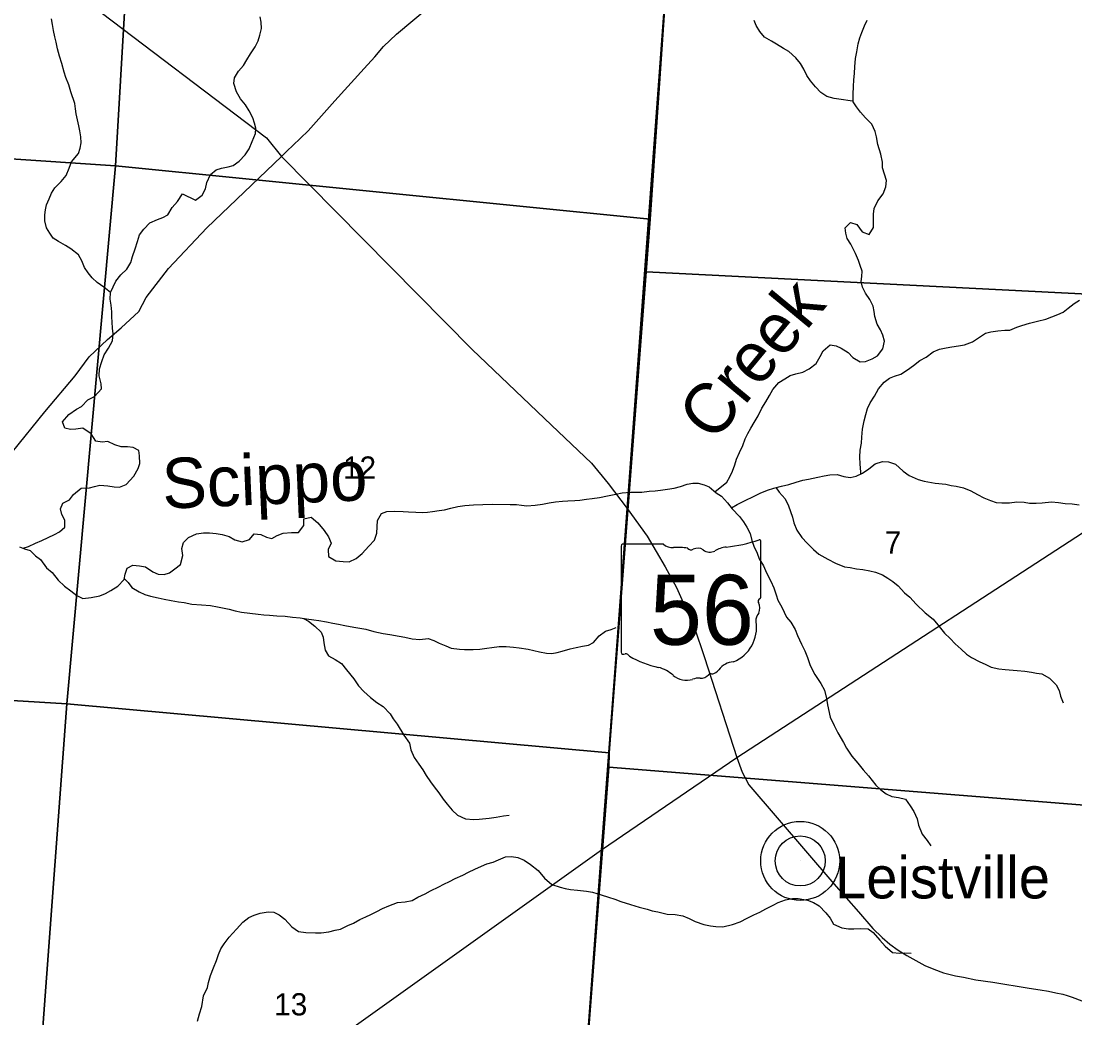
# Model space of a CAD drawing. Extents: x 1643459 to 2064572, y 425441 to 780708.
# Drawn here: x 1865157 to 1875648, y 555768 to 565687 of the extents above; entities that cross this region are included whole.
import ezdxf

# ---------------------------------------------------------------- set-up
doc = ezdxf.new("R2010")
doc.units = 0
for name, color, linetype in [('GE_P_Alignment_100_Curve_Data', 7, 'Continuous'), ('GM_X_Adjacent_County', 7, 'Continuous'), ('GM_X_City_Street', 7, 'Continuous'), ('GM_X_Interchange_Ramps', 7, 'Continuous'), ('GM_X_Major_River_Text', 7, 'Continuous'), ('GM_X_Rail_Line', 7, 'Continuous'), ('GM_X_State_Route', 7, 'Continuous'), ('GM_X_Township_ROW', 7, 'Continuous'), ('GM_X_US_Route', 7, 'Continuous'), ('PM_P_Cells', 7, 'Continuous'), ('RD_X_Text', 7, 'Continuous'), ('ST_Details', 7, 'Continuous')]:
    doc.layers.add(name, color=color, linetype=linetype)

msp = doc.modelspace()

# ---------------------------------------------------------------- linework, layer by layer
at = {"layer": 'GE_P_Alignment_100_Curve_Data'}
for radius in [393, 249]:
    msp.add_circle((1872913, 557330), radius, dxfattribs=at)
at = {"layer": 'GM_X_City_Street'}
for points in [[(1843248, 570866), (1845450, 570731), (1847249, 570616), (1849898, 570458), (1849968, 570443), (1850122, 570435), (1851230, 570338), (1851365, 570353), (1852697, 570271), (1853339, 570225), (1855635, 570110), (1855712, 570098), (1858092, 569921), (1858213, 569927), (1860143, 569780), (1863642, 569513), (1864565, 569438), (1866325, 569307), (1871699, 568906), (1871789, 568904), (1871189, 560836), (1870936, 557440), (1870510, 551709)], [(1891038, 535264), (1876915, 536283), (1869365, 536798), (1869625, 540128), (1869975, 544893), (1870294, 549051), (1870510, 551709), (1870936, 557440), (1871189, 560836), (1871789, 568904), (1872185, 568870), (1872796, 568823), (1874538, 568690), (1875303, 568632), (1876334, 568559), (1877076, 568501), (1882154, 568081), (1884543, 567856)]]:
    msp.add_lwpolyline(points, dxfattribs=at)
at = {"layer": 'GM_X_Major_River_Text'}
for points in [[(1867863, 564450), (1868014, 564595), (1868279, 564895), (1868572, 565216), (1868677, 565332), (1868764, 565434), (1868893, 565558), (1869238, 565847), (1869691, 566239), (1870084, 566568), (1870264, 566733), (1870344, 566797), (1870453, 566895), (1870614, 567065), (1871125, 567416)], [(1867749, 564341), (1867806, 564396), (1867863, 564450)], [(1864004, 560421), (1864119, 560508), (1864470, 560783), (1864563, 560848), (1864658, 560940), (1864778, 561043), (1865072, 561400), (1865395, 561800), (1865696, 562158), (1865834, 562345), (1866017, 562519), (1866154, 562636), (1866330, 562797), (1866402, 562938), (1866626, 563225), (1867005, 563630), (1867749, 564341)], [(1870510, 551709), (1870936, 557440)]]:
    msp.add_lwpolyline(points, dxfattribs=at)
at = {"layer": 'GM_X_Rail_Line'}
msp.add_line((1872913, 557330), (1872913, 557330), dxfattribs=at)
at = {"layer": 'GM_X_State_Route'}
for points in [[(1860886, 569691), (1860960, 569686), (1866313, 569289), (1866393, 569280), (1866098, 564247), (1860536, 564618)], [(1871776, 568888), (1871419, 563717), (1866098, 564247), (1866393, 569280)], [(1876329, 568549), (1877071, 568491), (1876694, 562925), (1871379, 563191), (1871419, 563717), (1871776, 568888)], [(1866098, 564247), (1865614, 558892), (1860164, 559226), (1860536, 564618)], [(1871419, 563717), (1871379, 563191), (1871012, 558406), (1865614, 558892), (1866098, 564247)], [(1876694, 562925), (1876279, 557842), (1871008, 558262), (1871012, 558406), (1871379, 563191)], [(1860164, 559226), (1865614, 558892), (1865211, 553484), (1859790, 553839)], [(1865614, 558892), (1871012, 558406), (1871008, 558262), (1870602, 552995), (1865211, 553484)], [(1871008, 558262), (1876279, 557842), (1875834, 552347), (1870578, 552653), (1870602, 552995)]]:
    msp.add_lwpolyline(points, close=True, dxfattribs=at)
at = {"layer": 'GM_X_US_Route'}
for points in [[(1866048, 562988), (1865982, 563040), (1865916, 563085), (1865865, 563133), (1865825, 563183), (1865787, 563236), (1865761, 563300), (1865727, 563361), (1865652, 563421), (1865598, 563454), (1865529, 563493), (1865477, 563527), (1865444, 563577), (1865410, 563630), (1865394, 563698), (1865394, 563758), (1865400, 563808), (1865411, 563858), (1865437, 563920), (1865459, 563974), (1865494, 564028), (1865557, 564090), (1865607, 564150), (1865636, 564224), (1865658, 564286), (1865727, 564368), (1865745, 564422), (1865755, 564476), (1865753, 564536), (1865743, 564594), (1865731, 564644), (1865717, 564703), (1865705, 564763), (1865699, 564813), (1865691, 564867), (1865651, 564982), (1865631, 565052), (1865603, 565127), (1865587, 565179), (1865563, 565265), (1865539, 565338), (1865521, 565410), (1865505, 565478), (1865493, 565529), (1865481, 565593), (1865471, 565653), (1865459, 565708)], [(1866764, 563967), (1866893, 563906), (1866958, 563956), (1866994, 564017), (1867007, 564082), (1867041, 564159), (1867098, 564207), (1867152, 564223), (1867217, 564236), (1867268, 564250), (1867328, 564292), (1867387, 564356), (1867428, 564417), (1867456, 564489), (1867492, 564567), (1867493, 564622), (1867481, 564672), (1867465, 564726), (1867428, 564795), (1867392, 564853), (1867342, 564914), (1867301, 564984), (1867275, 565066), (1867282, 565121), (1867320, 565190), (1867371, 565246), (1867403, 565300), (1867442, 565360), (1867486, 565432), (1867517, 565492), (1867535, 565546), (1867549, 565614), (1867547, 565678), (1867537, 565729)], [(1872064, 561003), (1872183, 561099), (1872213, 561151), (1872240, 561209), (1872262, 561271), (1872278, 561327), (1872309, 561393), (1872341, 561465), (1872366, 561529), (1872392, 561583), (1872420, 561635), (1872455, 561693), (1872493, 561759), (1872532, 561835), (1872572, 561899), (1872607, 561961), (1872639, 562021), (1872700, 562090), (1872759, 562126), (1872813, 562162), (1872870, 562178), (1872939, 562195), (1873001, 562227), (1873072, 562280), (1873111, 562348), (1873141, 562406), (1873212, 562466), (1873270, 562457), (1873321, 562433), (1873389, 562390), (1873436, 562338), (1873510, 562295), (1873563, 562299), (1873630, 562326), (1873684, 562356), (1873735, 562426), (1873751, 562502), (1873737, 562562), (1873711, 562615), (1873679, 562671), (1873655, 562746), (1873649, 562798), (1873639, 562852), (1873605, 562918), (1873564, 562979), (1873534, 563039), (1873520, 563095), (1873526, 563146), (1873529, 563198), (1873511, 563254), (1873492, 563306), (1873462, 563373), (1873416, 563467), (1873382, 563524), (1873368, 563576), (1873362, 563630), (1873412, 563684), (1873477, 563663), (1873529, 563591), (1873600, 563564), (1873641, 563634), (1873641, 563765), (1873649, 563823), (1873686, 563899), (1873738, 563968), (1873765, 564038), (1873771, 564101), (1873753, 564163), (1873733, 564227), (1873731, 564283), (1873715, 564362), (1873687, 564458), (1873671, 564535), (1873659, 564589), (1873625, 564663), (1873562, 564726), (1873514, 564782), (1873474, 564833), (1873441, 564885), (1873441, 564958), (1873444, 565038), (1873446, 565098), (1873452, 565168), (1873456, 565232), (1873464, 565316), (1873475, 565381), (1873491, 565461), (1873507, 565519), (1873528, 565573), (1873552, 565641), (1873580, 565697)], [(1873441, 564889), (1873411, 564892), (1873322, 564906), (1873250, 564917), (1873177, 564937), (1873118, 564976), (1873066, 565034), (1873014, 565091), (1872979, 565145), (1872949, 565210), (1872915, 565266), (1872871, 565323), (1872800, 565383), (1872748, 565416), (1872677, 565459), (1872627, 565487), (1872558, 565528), (1872512, 565584), (1872475, 565643), (1872455, 565693)], [(1865179, 560441), (1865230, 560458), (1865300, 560491), (1865365, 560517), (1865426, 560547), (1865488, 560578), (1865539, 560606), (1865591, 560650), (1865592, 560720), (1865561, 560778), (1865551, 560835), (1865574, 560891), (1865639, 560924), (1865679, 560976), (1865756, 561038), (1865837, 561043), (1865889, 561055), (1865940, 561070), (1866019, 561064), (1866085, 561051), (1866138, 561049), (1866204, 561077), (1866279, 561160), (1866322, 561234), (1866340, 561284), (1866336, 561362), (1866328, 561413), (1866274, 561443), (1866215, 561450), (1866153, 561452), (1866090, 561471), (1866020, 561503), (1865965, 561498), (1865900, 561508), (1865856, 561579), (1865771, 561635), (1865703, 561626), (1865650, 561624), (1865592, 561637), (1865568, 561701), (1865632, 561773), (1865707, 561824), (1865758, 561852), (1865822, 561920), (1865887, 561951), (1865958, 562027), (1865954, 562077), (1865934, 562156), (1865936, 562226), (1865961, 562300), (1865985, 562366), (1866026, 562434), (1866066, 562504), (1866074, 562574), (1866068, 562632), (1866064, 562690), (1866059, 562744), (1866059, 562795), (1866053, 562859), (1866043, 562921), (1866047, 562985), (1866100, 563099), (1866150, 563161), (1866209, 563217), (1866248, 563285), (1866266, 563345), (1866294, 563421), (1866315, 563495), (1866335, 563561), (1866378, 563617), (1866440, 563678), (1866515, 563714), (1866568, 563734), (1866618, 563759), (1866661, 563833), (1866713, 563893), (1866764, 563967)], [(1873518, 561181), (1873516, 561198), (1873510, 561280), (1873506, 561348), (1873511, 561417), (1873523, 561487), (1873525, 561547), (1873533, 561625), (1873548, 561709), (1873566, 561773), (1873584, 561833), (1873609, 561889), (1873653, 561955), (1873694, 562029), (1873748, 562093), (1873801, 562133), (1873851, 562154), (1873914, 562174), (1873981, 562218), (1874040, 562261), (1874104, 562309), (1874167, 562343), (1874236, 562396), (1874298, 562424), (1874365, 562435), (1874424, 562445), (1874488, 562455), (1874549, 562466), (1874628, 562494), (1874699, 562543), (1874757, 562583), (1874810, 562595), (1874881, 562604), (1874949, 562610), (1875000, 562613), (1875068, 562641), (1875119, 562659), (1875194, 562682), (1875275, 562700), (1875359, 562721), (1875418, 562743), (1875479, 562766), (1875529, 562792), (1875580, 562830), (1875641, 562878), (1875693, 562909)], [(1872230, 560843), (1872287, 560878), (1872364, 560917), (1872449, 560957), (1872516, 560989), (1872589, 561018), (1872649, 561038), (1872726, 561059), (1872799, 561077), (1872872, 561098), (1872940, 561118), (1872995, 561130), (1873088, 561149), (1873153, 561162), (1873207, 561172), (1873282, 561176), (1873348, 561155), (1873411, 561145), (1873470, 561158), (1873532, 561188), (1873597, 561233), (1873658, 561281), (1873733, 561305), (1873793, 561300), (1873862, 561278), (1873938, 561207), (1873999, 561164), (1874086, 561124), (1874148, 561109), (1874255, 561090), (1874362, 561078), (1874415, 561065), (1874467, 561059), (1874538, 561042), (1874613, 561014), (1874677, 560977), (1874742, 560944), (1874808, 560916), (1874863, 560897), (1874919, 560893), (1874998, 560894), (1875069, 560904), (1875141, 560899), (1875196, 560891), (1875261, 560890), (1875321, 560894), (1875416, 560903), (1875485, 560897), (1875549, 560888), (1875620, 560882), (1875689, 560875)], [(1868245, 560492), (1868215, 560428), (1868217, 560360), (1868291, 560317), (1868362, 560309), (1868424, 560306), (1868493, 560340), (1868554, 560388), (1868619, 560461), (1868675, 560523), (1868700, 560593), (1868702, 560655), (1868706, 560719), (1868745, 560787), (1868797, 560807), (1868870, 560812), (1868961, 560808), (1869013, 560803), (1869086, 560801), (1869151, 560798), (1869203, 560802), (1869254, 560806), (1869318, 560817), (1869373, 560825), (1869435, 560842), (1869504, 560856), (1869575, 560866), (1869660, 560873), (1869753, 560876), (1869852, 560880), (1870025, 560878), (1870088, 560876), (1870138, 560871), (1870193, 560865), (1870276, 560870), (1870346, 560880), (1870415, 560894), (1870476, 560903), (1870546, 560911), (1870599, 560912), (1870668, 560916), (1870720, 560919), (1870785, 560929), (1870841, 560937), (1870914, 560948), (1870995, 560964), (1871078, 560979), (1871140, 560993), (1871223, 560998), (1871278, 560998), (1871336, 561001), (1871409, 561009), (1871468, 561014), (1871522, 561020), (1871591, 561029), (1871658, 561039), (1871722, 561057), (1871787, 561078), (1871844, 561088), (1871896, 561089), (1871957, 561071), (1872007, 561052), (1872078, 560992), (1872128, 560959), (1872189, 560893), (1872237, 560834), (1872309, 560759), (1872348, 560703), (1872380, 560651), (1872414, 560588), (1872430, 560520), (1872452, 560462), (1872486, 560391), (1872506, 560337), (1872547, 560268), (1872579, 560196), (1872619, 560113), (1872649, 560049), (1872675, 559978), (1872691, 559926), (1872730, 559854), (1872778, 559757), (1872818, 559705), (1872862, 559632), (1872887, 559572), (1872925, 559487), (1872959, 559421), (1872987, 559356), (1873009, 559286), (1873031, 559236), (1873059, 559185), (1873118, 559095), (1873156, 559030), (1873176, 558946), (1873184, 558882), (1873210, 558761), (1873250, 558679), (1873288, 558604), (1873345, 558509), (1873373, 558451), (1873427, 558374)], [(1872673, 561044), (1872702, 560999), (1872762, 560933), (1872796, 560864), (1872816, 560806), (1872835, 560750), (1872849, 560695), (1872881, 560623), (1872929, 560550), (1872981, 560492), (1873044, 560429), (1873098, 560383), (1873189, 560334), (1873264, 560293), (1873355, 560258), (1873409, 560250), (1873474, 560237), (1873536, 560231), (1873607, 560218), (1873663, 560202), (1873732, 560177), (1873785, 560145), (1873835, 560110), (1873887, 560068), (1873950, 559999), (1874004, 559955), (1874067, 559884), (1874157, 559799), (1874238, 559736), (1874284, 559678), (1874351, 559597), (1874405, 559543), (1874456, 559490), (1874514, 559438), (1874567, 559387), (1874619, 559355), (1874702, 559310), (1874754, 559287), (1874815, 559259), (1874889, 559240), (1874954, 559234), (1875073, 559225), (1875150, 559218), (1875215, 559208), (1875265, 559200), (1875317, 559191), (1875396, 559150), (1875461, 559084), (1875491, 559027), (1875505, 558969), (1875529, 558903)], [(1865141, 560456), (1865191, 560436), (1865248, 560418), (1865300, 560365), (1865350, 560329), (1865409, 560246), (1865467, 560201), (1865526, 560123), (1865590, 560064), (1865653, 560017), (1865713, 559973), (1865772, 559942), (1865855, 559952), (1865941, 559969), (1865996, 559991), (1866051, 560021), (1866119, 560064), (1866182, 560130), (1866192, 560182), (1866213, 560242), (1866269, 560274), (1866336, 560267), (1866397, 560257), (1866469, 560206), (1866520, 560184), (1866580, 560181), (1866633, 560197), (1866689, 560237), (1866744, 560280), (1866768, 560368), (1866758, 560439), (1866773, 560499), (1866823, 560547), (1866904, 560584), (1866973, 560596), (1867033, 560595), (1867098, 560587), (1867159, 560578), (1867229, 560558), (1867286, 560525), (1867358, 560505), (1867431, 560528), (1867476, 560586), (1867544, 560577), (1867599, 560553), (1867653, 560540), (1867706, 560568), (1867765, 560590), (1867849, 560597), (1867920, 560597), (1867971, 560667), (1867973, 560735), (1868044, 560750), (1868112, 560694), (1868175, 560619), (1868217, 560556), (1868245, 560492)], [(1866184, 560140), (1866222, 560102), (1866261, 560051), (1866333, 560007), (1866390, 559980), (1866446, 559964), (1866521, 559947), (1866582, 559934), (1866650, 559922), (1866725, 559907), (1866779, 559901), (1866858, 559886), (1866953, 559880), (1867044, 559873), (1867111, 559860), (1867228, 559834), (1867288, 559819), (1867351, 559807), (1867434, 559796), (1867518, 559787), (1867573, 559779), (1867630, 559774), (1867702, 559770), (1867787, 559765), (1867858, 559757), (1867936, 559748), (1867999, 559740), (1868072, 559729), (1868122, 559721), (1868197, 559708), (1868260, 559696), (1868316, 559685), (1868379, 559673), (1868469, 559656), (1868528, 559646), (1868589, 559635), (1868667, 559614), (1868762, 559594), (1868827, 559583), (1868920, 559566), (1868978, 559558), (1869049, 559541), (1869126, 559535), (1869208, 559544), (1869265, 559524), (1869319, 559497), (1869386, 559471), (1869439, 559448), (1869521, 559438), (1869572, 559433), (1869659, 559435), (1869723, 559438), (1869792, 559448), (1869842, 559455), (1869917, 559465), (1869986, 559464), (1870059, 559458), (1870115, 559449), (1870204, 559437), (1870261, 559424), (1870317, 559410), (1870388, 559397), (1870440, 559395), (1870493, 559403), (1870543, 559416), (1870624, 559442), (1870683, 559453), (1870747, 559467), (1870804, 559477), (1870854, 559504), (1870913, 559570), (1870974, 559618), (1871030, 559633), (1871081, 559653)], [(1867968, 559744), (1868019, 559717), (1868082, 559667), (1868144, 559606), (1868164, 559556), (1868172, 559500), (1868184, 559427), (1868216, 559371), (1868283, 559334), (1868348, 559294), (1868398, 559231), (1868468, 559141), (1868515, 559074), (1868569, 559015), (1868636, 558957), (1868700, 558906), (1868761, 558866), (1868831, 558795), (1868861, 558745), (1868900, 558690), (1868966, 558581), (1869022, 558503), (1869038, 558436), (1869069, 558360), (1869117, 558293), (1869155, 558237), (1869191, 558180), (1869232, 558118), (1869268, 558068), (1869314, 558007), (1869359, 557945), (1869399, 557894), (1869449, 557836), (1869502, 557787), (1869582, 557748), (1869663, 557742), (1869718, 557745), (1869817, 557755), (1869887, 557764), (1869960, 557778), (1870015, 557787)], [(1873427, 558374), (1873486, 558304), (1873540, 558235), (1873592, 558177), (1873665, 558084), (1873717, 558037), (1873768, 557999), (1873824, 557970), (1873891, 557962), (1873960, 557945), (1874008, 557879), (1874044, 557822), (1874076, 557750), (1874092, 557686), (1874128, 557597), (1874177, 557532), (1874213, 557482)], [(1868639, 556798), (1868698, 556826), (1868754, 556856), (1868817, 556883), (1868904, 556917), (1868981, 556922), (1869049, 556938), (1869106, 556968), (1869181, 557003), (1869231, 557033), (1869314, 557072), (1869365, 557098), (1869423, 557124), (1869478, 557155), (1869555, 557189), (1869611, 557219), (1869674, 557248), (1869739, 557278), (1869793, 557300), (1869856, 557317), (1869909, 557341), (1869979, 557372), (1870038, 557374), (1870103, 557364), (1870165, 557337), (1870228, 557296), (1870306, 557236), (1870367, 557159), (1870441, 557096), (1870522, 557068), (1870572, 557055), (1870625, 557047), (1870696, 557038), (1870787, 557028), (1870845, 557019), (1870932, 556992), (1871005, 556968), (1871067, 556951), (1871128, 556927), (1871225, 556898), (1871309, 556869), (1871390, 556849), (1871440, 556834), (1871497, 556824), (1871590, 556801), (1871669, 556797), (1871743, 556784), (1871806, 556757), (1871866, 556729), (1871955, 556698), (1872020, 556684), (1872074, 556677), (1872143, 556673), (1872238, 556696), (1872315, 556724), (1872386, 556759), (1872452, 556793), (1872511, 556820), (1872572, 556854), (1872644, 556890), (1872695, 556917), (1872768, 556943), (1872836, 556957), (1872893, 556956), (1872984, 556939), (1873046, 556915), (1873101, 556884), (1873167, 556814), (1873210, 556761), (1873246, 556701), (1873327, 556666), (1873395, 556656), (1873448, 556655), (1873516, 556659), (1873589, 556656), (1873640, 556618), (1873704, 556541), (1873760, 556482), (1873831, 556420), (1873902, 556413), (1873952, 556417), (1874019, 556414)], [(1866912, 555736), (1866932, 555808), (1866955, 555882), (1866973, 555988), (1867014, 556070), (1867022, 556120), (1867042, 556190), (1867073, 556266), (1867101, 556338), (1867121, 556398), (1867146, 556454), (1867178, 556506), (1867229, 556572), (1867302, 556652), (1867366, 556721), (1867425, 556767), (1867476, 556789), (1867538, 556810), (1867615, 556824), (1867672, 556820), (1867726, 556793), (1867783, 556751), (1867851, 556676), (1867920, 556629), (1867990, 556619), (1868087, 556614), (1868144, 556616), (1868221, 556625), (1868285, 556641), (1868336, 556650), (1868411, 556688), (1868465, 556711), (1868530, 556747), (1868588, 556775), (1868639, 556798)]]:
    msp.add_lwpolyline(points, dxfattribs=at)
at = {"layer": 'RD_X_Text'}
for points in [[(1855870, 574227), (1856197, 573927), (1857624, 573064), (1858345, 571907), (1858655, 571415), (1859710, 570268), (1860143, 569780), (1862774, 568227), (1863103, 568005), (1863506, 567628), (1864111, 567169), (1867599, 564526), (1867749, 564341), (1869646, 562419), (1870438, 561665)], [(1853658, 538647), (1857824, 545139), (1858025, 545447), (1859784, 548105), (1860677, 549070), (1862259, 550763), (1863223, 551835), (1863365, 551991), (1867522, 555003), (1870936, 557440), (1872282, 558358), (1876521, 561111), (1878743, 562632), (1878993, 562781), (1879491, 563044), (1881881, 563743), (1885154, 564722), (1885648, 564775), (1886516, 564866), (1886708, 564902), (1886850, 564973), (1887258, 565264), (1887306, 565299)], [(1870438, 561665), (1870834, 561288), (1871002, 561086), (1871189, 560836), (1871388, 560563), (1871569, 560255), (1871683, 560050), (1871864, 559641), (1871952, 559374)], [(1871952, 559374), (1871959, 559356), (1872282, 558358)], [(1872282, 558358), (1872336, 558212), (1872402, 558088), (1873249, 557101), (1873494, 556822)], [(1873494, 556822), (1873636, 556659), (1873728, 556568), (1873804, 556501), (1873889, 556442), (1873974, 556389), (1874064, 556338), (1874154, 556291), (1874243, 556252), (1874338, 556217), (1874458, 556188), (1874537, 556173), (1874662, 556148), (1874832, 556124), (1875192, 556065), (1875301, 556047), (1875384, 556033), (1875459, 556019), (1875528, 556003), (1875571, 555990), (1875621, 555973), (1875715, 555939)]]:
    msp.add_lwpolyline(points, dxfattribs=at)
at = {"layer": 'ST_Details'}
for p, q in [((1871130, 560463), (1871130, 559407)), ((1871551, 560481), (1871143, 560481)), ((1872522, 559955), (1872522, 560508)), ((1872522, 559955), (1872522, 559955))]:
    msp.add_line(p, q, dxfattribs=at)
for centre, radius, start, end in [((1872026, 561922), 1476, 275.8445, 288.9065), ((1872506, 560510), 15.5, 351.8621, 97.738), ((1871146, 560466), 16.1, 98.1301, 188.1301), ((1871648, 560604), 156, 231.6195, 271.1119), ((1871700, 559888), 562, 80.4867, 94.9883), ((1871827, 560471), 45.1, 219.7921, 297.1024), ((1871894, 560349), 93.8, 54.4667, 119.1411), ((1872015, 560516), 113, 233.8562, 294.8282), ((1872214, 560159), 297, 97.3462, 120.7689), ((1872518, 559914), 24, 107.944, 210.337), ((1872366, 559844), 144, 340.033, 23.6496), ((1872505, 559953), 16.6, 289.6038, 7.7341), ((1872577, 559724), 105, 136.8065, 186.9296), ((1872109, 559653), 369, 292.3089, 8.9858), ((1871146, 559404), 16.3, 171.9584, 258.3066), ((1871148, 559512), 124, 267.339, 280.6039), ((1871174, 559346), 44.8, 29.7484, 93.2717), ((1871739, 560295), 1066, 240.4129, 257.1985), ((1872264, 559110), 202, 94.4031, 142.5768), ((1871421, 558932), 334, 47.1842, 75.836), ((1871782, 559340), 212, 230.7004, 286.2918), ((1871920, 559261), 113, 268.777, 315.5493), ((1872022, 559159), 31.8, 65.7517, 132.6484), ((1872008, 559304), 119, 282.8732, 323.2771), ((1871904, 558975), 174, 85.6951, 111.2099)]:
    msp.add_arc(centre, radius, start, end, dxfattribs=at)

# ---------------------------------------------------------------- texts
at = {"layer": 'GM_X_Adjacent_County'}
for s, p in [('12', (1868362, 561134)), ('7', (1873754, 560388)), ('13', (1867677, 555793))]:
    msp.add_text(s, height=221, rotation=0, dxfattribs=at).set_placement(p)
at = {"layer": 'GM_X_Interchange_Ramps'}
for s, rotation, p in [('Creek', 50.453, (1872049, 561482)), ('Scippo', 2.4509, (1866570, 560834))]:
    msp.add_text(s, height=500, rotation=rotation, dxfattribs=at).set_placement(p)
at = {"layer": 'GM_X_Township_ROW'}
msp.add_text('Leistville', height=417, rotation=0, dxfattribs=at).set_placement((1873261, 556957))
at = {"layer": 'PM_P_Cells'}
msp.add_text('56', height=1, rotation=0, dxfattribs=at).set_placement((1871558, 559792))
for s in ['s', 'r']:
    msp.add_text(s, height=1, dxfattribs=at).set_placement((1871810, 559865))
at = {"layer": 'ST_Details'}
msp.add_text('56', height=696.1, dxfattribs=at).set_placement((1871417, 559481))

doc.saveas('drawing.dxf')
